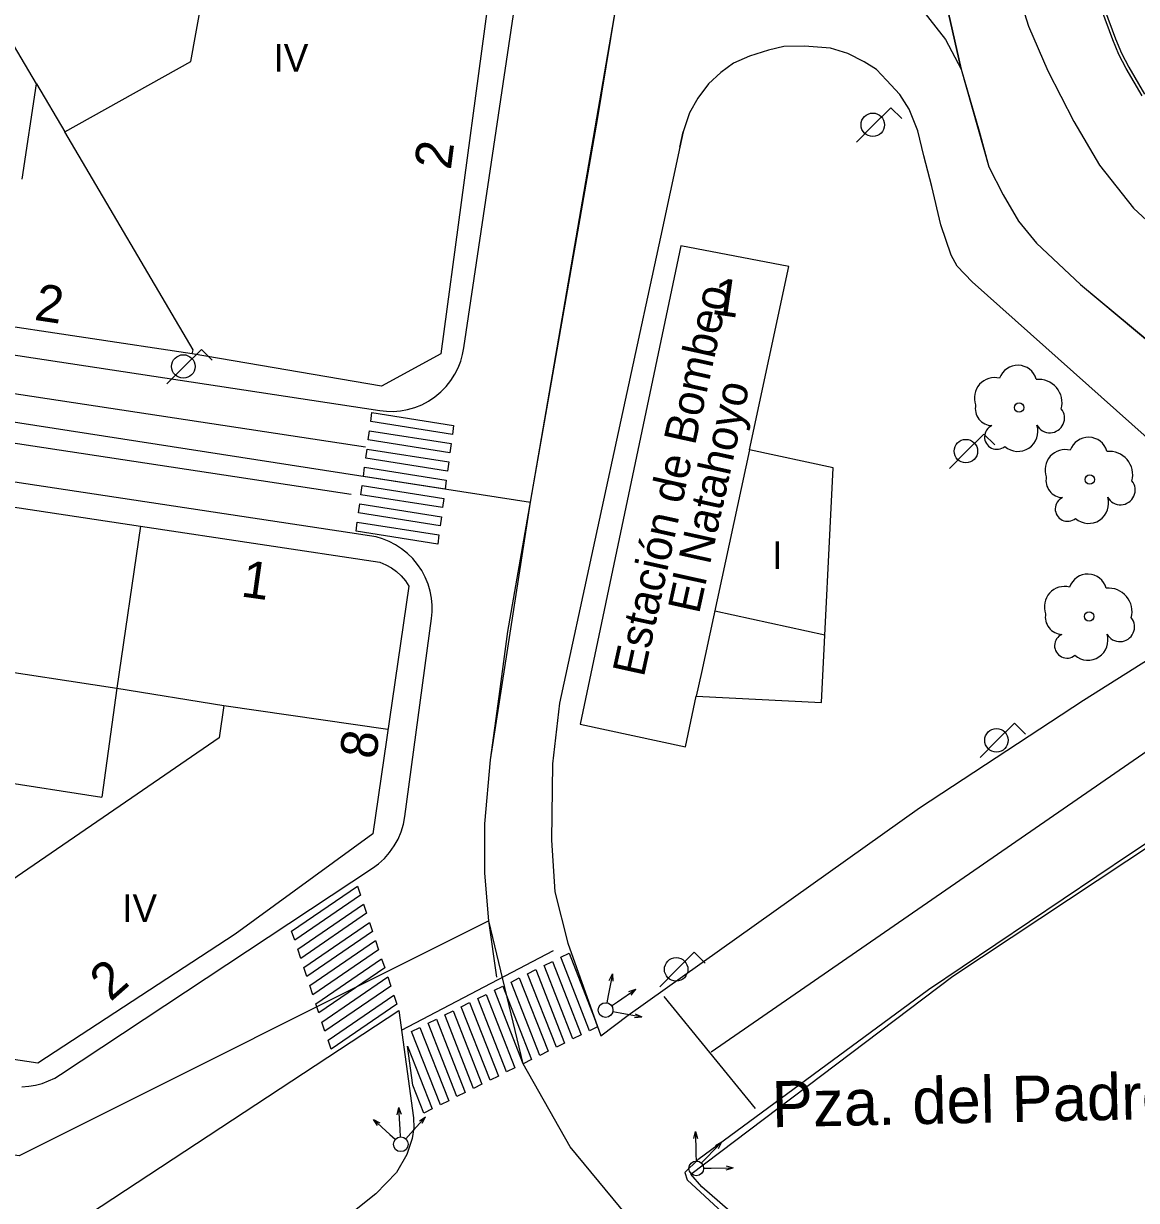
# Model space of a CAD drawing. Extents: x 282771 to 285132, y 4823109 to 4825496.
# Drawn here: x 283576.8 to 283637.2, y 4824199.4 to 4824263.2 of the extents above; entities that cross this region are included whole.
import ezdxf

# ---------------------------------------------------------------- set-up
doc = ezdxf.new("R2010")
doc.units = 0
for name, color, linetype in [('ACERA-BORDILLO', 7, 'Continuous'), ('ACERA-INTERIOR', 7, 'Continuous'), ('ARBOL', 7, 'Continuous'), ('BORDILLO', 7, 'Continuous'), ('CALLE-EJE', 7, 'Continuous'), ('CALLE-TEXTO', 7, 'Continuous'), ('EDIFICIO', 7, 'Continuous'), ('FAROLA', 7, 'Continuous'), ('INTERIOR-EDIFICIO', 7, 'Continuous'), ('MEDIANERA', 7, 'Continuous'), ('NUM-LOCAL', 7, 'Continuous'), ('NUM-PORTAL', 7, 'Continuous'), ('PASO-PEATONES', 7, 'Continuous'), ('SEMAFORO', 7, 'Continuous'), ('SENAL-VIARIA', 7, 'Continuous'), ('TXT-ALTURA-EDIFICIO', 7, 'Continuous'), ('TXT-EDIFICIOS', 7, 'Continuous'), ('ZONA-VERDE', 7, 'Continuous')]:
    doc.layers.add(name, color=color, linetype=linetype)

msp = doc.modelspace()

# ---------------------------------------------------------------- linework, layer by layer
at = {"layer": 'ACERA-BORDILLO'}
for points in [[(283600.686, 4824245.623), (283604.195, 4824269.193), (283604.387, 4824270.405), (283604.402, 4824270.967), (283604.387, 4824271.499), (283604.357, 4824271.943), (283604.283, 4824272.357), (283604.047, 4824272.844), (283603.766, 4824273.318), (283603.396, 4824273.761), (283602.879, 4824274.205), (283602.391, 4824274.545), (283601.815, 4824274.781), (283598.429, 4824275.284), (283597.35, 4824274.397), (283540.343, 4824283.26)], [(283637.388, 4824275.487), (283632.963, 4824275.002), (283632.223, 4824274.832), (283631.583, 4824274.402), (283630.823, 4824273.552), (283630.463, 4824272.882), (283630.203, 4824271.782), (283630.193, 4824270.537), (283630.237, 4824269.274), (283630.337, 4824267.995), (283630.495, 4824266.705), (283630.713, 4824265.406), (283630.992, 4824264.104), (283631.322, 4824263.084), (283632.369, 4824260.665), (283633.767, 4824257.907), (283635.164, 4824255.541), (283637.018, 4824253.203), (283638.926, 4824251.428)], [(283476.022, 4824260.472), (283596.123, 4824242.22), (283596.483, 4824242.182), (283596.858, 4824242.177), (283597.242, 4824242.208), (283597.631, 4824242.279), (283598.02, 4824242.39), (283598.401, 4824242.543), (283598.768, 4824242.736), (283599.115, 4824242.968), (283599.436, 4824243.235), (283599.726, 4824243.531), (283599.982, 4824243.853), (283600.199, 4824244.194), (283600.378, 4824244.547), (283600.518, 4824244.906), (283600.62, 4824245.267), (283600.686, 4824245.623)], [(283595.57, 4824235.434), (283594.509, 4824235.594), (283472.994, 4824253.972)], [(283576.712, 4824205.531), (283577.082, 4824205.559), (283577.449, 4824205.622), (283577.809, 4824205.718), (283578.157, 4824205.847), (283578.489, 4824206.006), (283578.801, 4824206.193), (283595.728, 4824217.388), (283596.064, 4824217.636), (283596.377, 4824217.923), (283596.661, 4824218.245), (283596.91, 4824218.598), (283597.12, 4824218.976), (283597.286, 4824219.372), (283597.408, 4824219.779), (283597.486, 4824220.189), (283598.936, 4824230.944), (283598.968, 4824231.3), (283598.968, 4824231.668), (283598.932, 4824232.046), (283598.858, 4824232.427), (283598.745, 4824232.808), (283598.592, 4824233.18), (283598.401, 4824233.539), (283598.172, 4824233.878), (283597.911, 4824234.193), (283597.62, 4824234.477), (283597.305, 4824234.728), (283596.972, 4824234.943), (283596.626, 4824235.121), (283596.274, 4824235.261), (283595.92, 4824235.365), (283595.57, 4824235.434)], [(283374.187, 4824226.536), (283555.674, 4824199.16), (283557.751, 4824201.29), (283578.283, 4824198.192), (283580.373, 4824198.642), (283597.161, 4824209.67), (283597.959, 4824203.844), (283597.965, 4824203.302), (283597.873, 4824202.732), (283597.6, 4824201.866), (283597.03, 4824200.885), (283595.914, 4824199.722), (283594.489, 4824198.577), (283578.033, 4824188.752), (283575.593, 4824187.492), (283555.424, 4824180.683), (283529.014, 4824171.443), (283491.581, 4824157.904), (283488.412, 4824160.306), (283476.414, 4824155.967), (283475.409, 4824152.055), (283330.856, 4824099.773)]]:
    msp.add_lwpolyline(points, dxfattribs=at)
at = {"layer": 'ACERA-INTERIOR'}
msp.add_lwpolyline([(283637.478, 4824259.307), (283636.623, 4824260.792), (283636.223, 4824261.552), (283635.893, 4824262.342), (283635.293, 4824263.947), (283635.023, 4824264.762), (283634.623, 4824266.422), (283634.353, 4824268.122), (283634.128, 4824270.19), (283645.777, 4824272.409)], dxfattribs=at)
at = {"layer": 'ARBOL'}
for centre in [(283630.804, 4824242.385), (283634.638, 4824238.478), (283634.602, 4824231.055)]:
    msp.add_circle(centre, 0.255, dxfattribs=at)
for centre, radius, start, end in [((283630.734, 4824243.645), 1.038, 15.64228, 161.38435), ((283629.474, 4824242.915), 1.097, 75.4318, 200.55608), ((283631.864, 4824242.645), 1.272, 345.03273, 95.79925), ((283629.364, 4824242.345), 0.935, 168.59898, 268.13236), ((283632.474, 4824241.815), 0.797, 208.96247, 38.99103), ((283629.604, 4824240.795), 0.672, 113.73672, 309.4725), ((283630.744, 4824241.095), 1.086, 228.95447, 17.92796), ((283634.568, 4824239.738), 1.038, 15.64228, 161.38435), ((283633.308, 4824239.008), 1.097, 75.4318, 200.55608), ((283635.698, 4824238.738), 1.272, 345.03273, 95.79925), ((283633.198, 4824238.438), 0.935, 168.59898, 268.13236), ((283636.308, 4824237.908), 0.797, 208.96247, 38.99103), ((283633.438, 4824236.888), 0.672, 113.73672, 309.4725), ((283634.578, 4824237.188), 1.086, 228.95447, 17.92796), ((283634.532, 4824232.314), 1.038, 15.64228, 161.38435), ((283633.272, 4824231.584), 1.097, 75.4318, 200.55608), ((283635.662, 4824231.314), 1.272, 345.03273, 95.79925), ((283633.162, 4824231.015), 0.935, 168.59898, 268.13236), ((283636.272, 4824230.485), 0.797, 208.96247, 38.99103), ((283633.402, 4824229.465), 0.672, 113.73672, 309.4725), ((283634.542, 4824229.765), 1.086, 228.95447, 17.92796)]:
    msp.add_arc(centre, radius, start, end, dxfattribs=at)
at = {"layer": 'BORDILLO'}
for points in [[(283641.58, 4824237.323), (283628.253, 4824249.204), (283627.452, 4824250.053), (283627.114, 4824250.652), (283626.562, 4824252.295), (283626.07, 4824254.384), (283625.638, 4824256.04), (283625.315, 4824257.407), (283624.839, 4824258.575), (283624.333, 4824259.373), (283623.611, 4824260.142), (283623.074, 4824260.725), (283622.398, 4824261.14), (283621.507, 4824261.601), (283620.571, 4824261.893), (283619.158, 4824262), (283618.038, 4824261.969), (283617.208, 4824261.77), (283616.18, 4824261.462), (283615.32, 4824261.078), (283614.629, 4824260.572), (283613.953, 4824259.957), (283613.37, 4824259.174), (283612.921, 4824258.376), (283612.579, 4824257.34), (283612.407, 4824256.524), (283612.579, 4824257.34)], [(283612.407, 4824256.524), (283611.359, 4824251.632), (283605.876, 4824226.344), (283605.496, 4824223.053), (283605.442, 4824218.914), (283605.63, 4824216.118), (283606.329, 4824213.323), (283608.108, 4824208.304), (283609.602, 4824209.425), (283625.406, 4824220.661), (283634.294, 4824226.517), (283641.537, 4824231.067)], [(283640.881, 4824220.857), (283636.858, 4824218.169), (283625.895, 4824210.798), (283613.382, 4824201.57), (283612.676, 4824200.878), (283612.799, 4824200.479)], [(283612.799, 4824200.479), (283614.718, 4824198.705), (283618.372, 4824195.633), (283622.026, 4824193.206), (283625.682, 4824191.243), (283628.76, 4824189.993), (283632.819, 4824188.967), (283635.898, 4824188.386), (283638.931, 4824188.029)]]:
    msp.add_lwpolyline(points, dxfattribs=at)
at = {"layer": 'CALLE-EJE'}
for points in [[(283604.299, 4824237.26), (283611.064, 4824276.435)], [(283623.463, 4824276.152), (283626.508, 4824265.884), (283627.666, 4824260.75), (283629.171, 4824255.454), (283629.95, 4824253.922), (283630.783, 4824252.497), (283631.75, 4824251.315), (283634.141, 4824249.057), (283650.523, 4824235.462)], [(283468.214, 4824258.402), (283604.299, 4824237.26)], [(283602.045, 4824214.536), (283601.83, 4824217.116), (283601.83, 4824219.804), (283602.126, 4824223.272), (283604.299, 4824237.26)], [(283602.045, 4824214.536), (283576.563, 4824201.792), (283461.435, 4824217.883)], [(283615.3, 4824193.37), (283609.912, 4824198.103), (283606.452, 4824202.267), (283603.907, 4824206.785), (283602.045, 4824214.536)]]:
    msp.add_lwpolyline(points, dxfattribs=at)
at = {"layer": 'EDIFICIO'}
for points in [[(283570.937, 4824276.617), (283600.847, 4824272.182), (283602.74, 4824269.956), (283599.428, 4824245.304), (283596.209, 4824243.552), (283585.953, 4824245.302), (283568.623, 4824247.912)], [(283612.463, 4824251.162), (283606.993, 4824225.212), (283612.703, 4824223.972), (283613.297, 4824226.726), (283620.084, 4824226.391), (283620.712, 4824239.114), (283616.179, 4824240.092), (283618.323, 4824250.032), (283612.463, 4824251.162)], [(283568.044, 4824238.232), (283583.153, 4824235.952), (283596.133, 4824233.992), (283596.453, 4824233.862), (283596.753, 4824233.692), (283597.033, 4824233.492), (283597.283, 4824233.252), (283597.513, 4824232.992), (283597.693, 4824232.702), (283595.75, 4824219.264), (283588.273, 4824213.812), (283577.583, 4824206.822), (283572.893, 4824207.522)]]:
    msp.add_lwpolyline(points, dxfattribs=at)
at = {"layer": 'FAROLA'}
for p, q in [((283623.849, 4824258.658), (283622.909, 4824257.728)), ((283624.439, 4824258.068), (283623.849, 4824258.658)), ((283622.909, 4824257.728), (283621.979, 4824256.788)), ((283586.449, 4824245.545), (283585.509, 4824244.615)), ((283587.039, 4824244.955), (283586.449, 4824245.545)), ((283585.509, 4824244.615), (283584.579, 4824243.675)), ((283628.898, 4824240.952), (283627.958, 4824240.022)), ((283629.488, 4824240.362), (283628.898, 4824240.952)), ((283627.958, 4824240.022), (283627.028, 4824239.082)), ((283630.559, 4824225.264), (283629.619, 4824224.334)), ((283631.149, 4824224.674), (283630.559, 4824225.264)), ((283629.619, 4824224.334), (283628.689, 4824223.394)), ((283613.183, 4824212.832), (283612.243, 4824211.902)), ((283613.773, 4824212.242), (283613.183, 4824212.832)), ((283612.243, 4824211.902), (283611.313, 4824210.962))]:
    msp.add_line(p, q, dxfattribs=at)
for centre in [(283622.869, 4824257.728), (283585.469, 4824244.615), (283627.918, 4824240.022), (283629.579, 4824224.334), (283612.203, 4824211.902)]:
    msp.add_circle(centre, 0.637, dxfattribs=at)
at = {"layer": 'INTERIOR-EDIFICIO'}
for points in [[(283576.723, 4824254.772), (283577.501, 4824259.946), (283579.033, 4824257.343), (283585.882, 4824261.169), (283586.449, 4824264.37), (283563.009, 4824267.846)], [(283566.596, 4824229.472), (283574.257, 4824228.311), (283581.867, 4824227.158), (283587.662, 4824226.219), (283587.408, 4824224.459), (283582.961, 4824221.413), (283575.17, 4824216.078), (283574.264, 4824216.221), (283558.404, 4824218.762), (283547.414, 4824220.232), (283548.104, 4824226.352), (283543.274, 4824227.322), (283542.455, 4824222.022), (283534.206, 4824223.209), (283526.342, 4824224.341), (283527.034, 4824229.862), (283534.914, 4824228.562), (283539.124, 4824227.882), (283539.844, 4824232.852), (283543.296, 4824232.452), (283543.029, 4824230.711), (283548.704, 4824229.662), (283550.254, 4824229.405)]]:
    msp.add_lwpolyline(points, dxfattribs=at)
at = {"layer": 'MEDIANERA'}
for points in [[(283577.501, 4824259.946), (283575.833, 4824262.782)], [(283585.953, 4824245.302), (283585.993, 4824245.512), (283579.033, 4824257.343)], [(283616.179, 4824240.092), (283613.573, 4824228.012), (283613.297, 4824226.726)], [(283583.153, 4824235.952), (283581.867, 4824227.158)], [(283614.296, 4824231.361), (283620.265, 4824230.05)], [(283581.867, 4824227.158), (283581.051, 4824221.238)], [(283587.662, 4824226.219), (283596.57, 4824224.932)], [(283575.216, 4824222.157), (283581.051, 4824221.238)]]:
    msp.add_lwpolyline(points, dxfattribs=at)
at = {"layer": 'PASO-PEATONES'}
for points in [[(283600.061, 4824240.924), (283595.633, 4824241.623), (283595.699, 4824242.118), (283600.128, 4824241.42)], [(283599.929, 4824239.933), (283595.5, 4824240.631), (283595.566, 4824241.127), (283599.995, 4824240.429)], [(283599.796, 4824238.942), (283595.367, 4824239.64), (283595.434, 4824240.136), (283599.862, 4824239.437)], [(283599.663, 4824237.95), (283595.234, 4824238.648), (283595.301, 4824239.144), (283599.73, 4824238.446)], [(283599.531, 4824236.959), (283595.102, 4824237.657), (283595.168, 4824238.153), (283599.597, 4824237.454)], [(283599.398, 4824235.967), (283594.969, 4824236.666), (283595.035, 4824237.161), (283599.464, 4824236.463)], [(283599.265, 4824234.976), (283594.836, 4824235.674), (283594.903, 4824236.17), (283599.331, 4824235.472)], [(283591.509, 4824213.488), (283591.344, 4824213.982), (283594.912, 4824216.426), (283595.076, 4824215.932)], [(283591.837, 4824212.501), (283591.673, 4824212.995), (283595.241, 4824215.439), (283595.405, 4824214.945)], [(283592.166, 4824211.514), (283592.002, 4824212.008), (283595.569, 4824214.452), (283595.734, 4824213.958)], [(283592.495, 4824210.527), (283592.33, 4824211.021), (283595.898, 4824213.465), (283596.062, 4824212.971)], [(283592.823, 4824209.54), (283592.659, 4824210.034), (283596.226, 4824212.478), (283596.391, 4824211.984)], [(283605.941, 4824212.558), (283606.39, 4824212.781), (283607.759, 4824209.29), (283607.936, 4824208.789), (283607.502, 4824208.574)], [(283604.143, 4824211.664), (283604.593, 4824211.887), (283606.154, 4824207.903), (283605.704, 4824207.68)], [(283605.042, 4824212.111), (283605.492, 4824212.334), (283607.053, 4824208.35), (283606.603, 4824208.127)], [(283593.152, 4824208.553), (283592.987, 4824209.047), (283596.555, 4824211.491), (283596.719, 4824210.997)], [(283603.245, 4824211.217), (283603.694, 4824211.44), (283605.255, 4824207.456), (283604.806, 4824207.232)], [(283596.884, 4824210.504), (283597.048, 4824210.01), (283593.48, 4824207.566), (283593.316, 4824208.06)], [(283603.457, 4824206.562), (283603.008, 4824206.338), (283601.447, 4824210.322), (283601.896, 4824210.546)], [(283602.346, 4824210.77), (283602.795, 4824210.993), (283604.356, 4824207.009), (283603.907, 4824206.785)], [(283602.559, 4824206.115), (283602.109, 4824205.891), (283600.548, 4824209.875), (283600.997, 4824210.099)], [(283600.761, 4824205.221), (283600.311, 4824204.997), (283598.75, 4824208.981), (283599.2, 4824209.205)], [(283601.66, 4824205.668), (283601.21, 4824205.444), (283599.649, 4824209.428), (283600.099, 4824209.652)], [(283599.862, 4824204.774), (283599.412, 4824204.55), (283597.851, 4824208.534), (283598.301, 4824208.758)], [(283598.514, 4824204.103), (283597.917, 4824205.626), (283597.628, 4824207.733), (283598.963, 4824204.327)]]:
    msp.add_lwpolyline(points, close=True, dxfattribs=at)
at = {"layer": 'SEMAFORO'}
for p, q in [((283608.742, 4824211.661), (283608.52, 4824210.482)), ((283608.573, 4824211.306), (283608.742, 4824211.661)), ((283608.742, 4824211.661), (283608.77, 4824211.269)), ((283608.52, 4824210.482), (283608.446, 4824210.089)), ((283609.026, 4824210.142), (283610.018, 4824210.821)), ((283609.639, 4824210.698), (283610.018, 4824210.821)), ((283609.767, 4824210.512), (283610.018, 4824210.821)), ((283608.699, 4824209.919), (283609.026, 4824210.142)), ((283608.765, 4824209.622), (283609.158, 4824209.548)), ((283609.158, 4824209.548), (283610.338, 4824209.326)), ((283609.946, 4824209.298), (283610.338, 4824209.326)), ((283609.983, 4824209.494), (283610.338, 4824209.326)), ((283597.069, 4824204.019), (283597.162, 4824204.406)), ((283597.224, 4824203.206), (283597.162, 4824204.406)), ((283597.295, 4824204.031), (283597.162, 4824204.406)), ((283595.78, 4824203.754), (283596.671, 4824202.95)), ((283595.78, 4824203.754), (283596.129, 4824203.573)), ((283595.995, 4824203.425), (283595.78, 4824203.754)), ((283597.801, 4824203.009), (283598.604, 4824203.9)), ((283598.276, 4824203.685), (283598.604, 4824203.9)), ((283598.424, 4824203.551), (283598.604, 4824203.9)), ((283596.671, 4824202.95), (283596.968, 4824202.682)), ((283597.245, 4824202.81), (283597.224, 4824203.206)), ((283597.533, 4824202.712), (283597.801, 4824203.009)), ((283613.16, 4824202.72), (283613.253, 4824203.102)), ((283613.253, 4824203.102), (283613.277, 4824201.902)), ((283613.253, 4824203.102), (283613.36, 4824202.724)), ((283613.842, 4824201.674), (283614.674, 4824202.541)), ((283614.328, 4824202.344), (283614.674, 4824202.541)), ((283614.491, 4824202.187), (283614.674, 4824202.541)), ((283613.277, 4824201.902), (283613.285, 4824201.502)), ((283613.567, 4824201.388), (283613.842, 4824201.674)), ((283613.693, 4824201.11), (283614.093, 4824201.119)), ((283614.093, 4824201.119), (283615.293, 4824201.143)), ((283614.911, 4824201.235), (283615.293, 4824201.143)), ((283614.915, 4824201.035), (283615.293, 4824201.143))]:
    msp.add_line(p, q, dxfattribs=at)
for centre in [(283608.372, 4824209.695), (283597.265, 4824202.415), (283613.293, 4824201.102)]:
    msp.add_circle(centre, 0.4, dxfattribs=at)
at = {"layer": 'SENAL-VIARIA'}
for points in [[(283623.931, 4824265.83), (283625.436, 4824264.11), (283626.806, 4824262.363), (283627.666, 4824260.75), (283626.508, 4824265.884)], [(283601.83, 4824219.804), (283602.126, 4824223.272), (283602.609, 4824226.713), (283603.066, 4824230.234), (283607.943, 4824258.022), (283609.138, 4824265.283)], [(283475.669, 4824260.542), (283475.413, 4824258.466), (283595.342, 4824240.259)], [(283627.666, 4824260.75), (283628.633, 4824257.39), (283629.171, 4824255.454), (283629.95, 4824253.922), (283630.783, 4824252.497), (283631.75, 4824251.315), (283634.141, 4824249.057)], [(283474.313, 4824253.803), (283474.636, 4824255.899), (283594.565, 4824237.692)], [(283634.141, 4824249.057), (283643.204, 4824241.483)], [(283614.107, 4824207.43), (283642.367, 4824226.952)], [(283602.475, 4824211.471), (283602.045, 4824214.536), (283601.83, 4824217.116), (283601.83, 4824219.804)], [(283597.307, 4824208.605), (283605.55, 4824212.919)], [(283611.537, 4824210.44), (283616.497, 4824204.358)]]:
    msp.add_lwpolyline(points, dxfattribs=at)
at = {"layer": 'ZONA-VERDE'}
for p, q in [((283613.005, 4824200.782), (283627.213, 4824211.537)), ((283613.6, 4824200.107), (283613.005, 4824200.782)), ((283615.545, 4824198.401), (283613.6, 4824200.107))]:
    msp.add_line(p, q, dxfattribs=at)
for points in [[(283634.292, 4824270.069), (283634.502, 4824268.142), (283634.77, 4824266.451), (283635.167, 4824264.803), (283635.434, 4824263.997), (283636.032, 4824262.397), (283636.359, 4824261.616), (283636.754, 4824260.864), (283637.605, 4824259.387)], [(283627.213, 4824211.537), (283638.209, 4824218.83), (283641.909, 4824221.241), (283643.167, 4824221.697)]]:
    msp.add_lwpolyline(points, dxfattribs=at)

# ---------------------------------------------------------------- texts
at = {"layer": 'CALLE-TEXTO'}
msp.add_text('Pza. del Padre Máximo González', height=2.5, rotation=1.24745, dxfattribs=at).set_placement((283617.418, 4824203.333))
at = {"layer": 'NUM-LOCAL'}
for s, rotation, p in [('1', 351.71004, (283614.069, 4824247.478)), ('8', 82.45452, (283595.92, 4824223.26))]:
    msp.add_text(s, height=2, rotation=rotation, dxfattribs=at).set_placement(p)
at = {"layer": 'NUM-PORTAL'}
for s, rotation, p in [('2', 82.53241, (283599.973, 4824255.243)), ('2', 351.44004, (283577.332, 4824247.152)), ('1', 351.93004, (283588.543, 4824232.146)), ('2', 41.46004, (283581.518, 4824210.117))]:
    msp.add_text(s, height=2, rotation=rotation, dxfattribs=at).set_placement(p)
at = {"layer": 'TXT-ALTURA-EDIFICIO'}
for s, p in [('IV', (283590.355, 4824260.608)), ('I', (283617.412, 4824233.632)), ('IV', (283582.15, 4824214.482))]:
    msp.add_text(s, height=1.5, rotation=0.00004, dxfattribs=at).set_placement(p)
at = {"layer": 'TXT-EDIFICIOS'}
for s, p in [('Estación de Bombeo ', (283610.443, 4824227.718)), ('El Natahoyo', (283613.441, 4824231.145))]:
    msp.add_text(s, height=1.75, rotation=77.53828, dxfattribs=at).set_placement(p)

doc.saveas('drawing.dxf')
